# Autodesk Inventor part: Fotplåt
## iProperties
Created: 2006-04
Part Number: Fotplåt
Document SubType Name: Modeling
Designer: Helene
Density: 1 g/cm^3
Author: Helene
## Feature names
1. Extrusion1
2. Extrusion2
